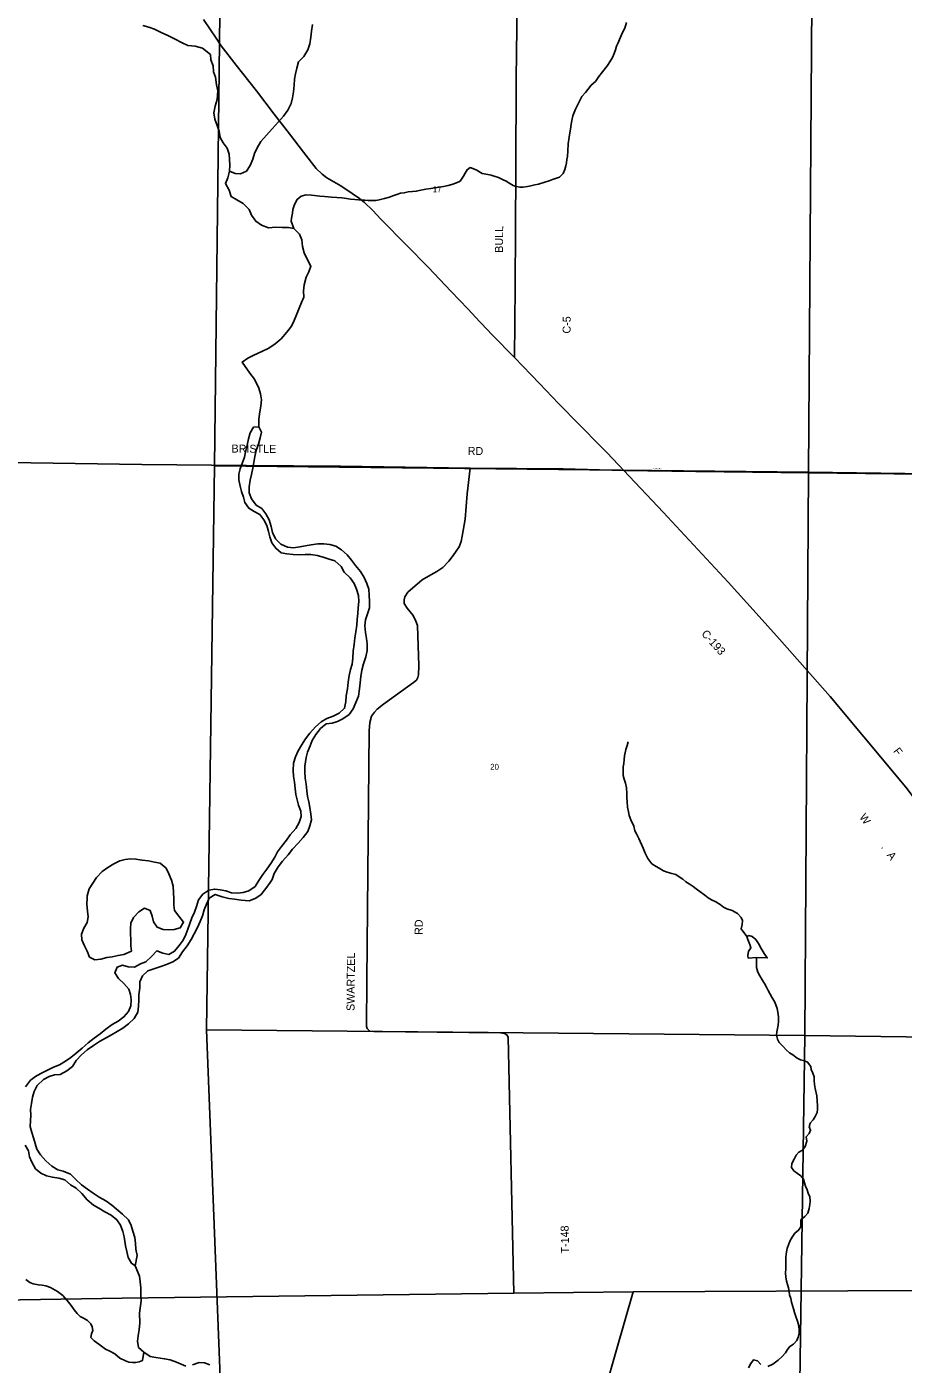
# Model space of a CAD drawing. Extents: x 1312308 to 1684953, y 460642 to 865172.
# Drawn here: x 1414657 to 1422870, y 616453 to 628989 of the extents above; entities that cross this region are included whole.
import ezdxf

# ---------------------------------------------------------------- set-up
doc = ezdxf.new("R2010")
doc.units = 0
for name, color, linetype in [('GM_X_County_Road', 7, 'Continuous'), ('GM_X_County_Road_Text', 7, 'Continuous'), ('GM_X_Minor_Lake', 7, 'Continuous'), ('GM_X_Minor_River', 7, 'Continuous'), ('GM_X_Section', 7, 'Continuous'), ('GM_X_Section_Text', 7, 'Continuous'), ('GM_X_Township_Road', 7, 'Continuous'), ('GM_X_Township_Road_Text', 7, 'Continuous'), ('GM_X_Township_Subdivision', 7, 'Continuous'), ('GM_X_Township_Subdivision_Text', 7, 'Continuous')]:
    doc.layers.add(name, color=color, linetype=linetype)

msp = doc.modelspace()

# ---------------------------------------------------------------- linework, layer by layer
at = {"layer": 'GM_X_County_Road'}
for points in [[(1419227, 625888), (1419235, 626551), (1419240, 627640), (1419244, 628500), (1419255, 629461), (1419265, 630495), (1419286, 631639), (1419313, 632893), (1419330, 633738), (1419360, 635102), (1419398, 637174), (1419431, 638484), (1419476, 640819), (1419479, 641151), (1419467, 641208), (1419429, 641336), (1419368, 641511)], [(1418902, 626224), (1418790, 626345), (1418634, 626507), (1418417, 626735), (1418214, 626941), (1417975, 627186), (1417900, 627265), (1417821, 627341), (1417775, 627379), (1417707, 627427), (1417601, 627498), (1417470, 627573), (1417424, 627608), (1417369, 627661), (1417251, 627812), (1417120, 627984), (1416976, 628169), (1416809, 628388), (1416737, 628478), (1416619, 628629), (1416479, 628811), (1416431, 628882), (1416312, 629056)], [(1420032, 625057), (1419835, 625257), (1419640, 625459), (1419463, 625645), (1419227, 625888), (1419018, 626102), (1418914, 626211), (1418902, 626224)], [(1425179, 618809), (1424819, 619478), (1424794, 619514), (1424735, 619589), (1424329, 620045), (1423843, 620591), (1423757, 620694), (1423588, 620906), (1423489, 621044), (1423310, 621295), (1423032, 621677), (1422907, 621845), (1422722, 622068), (1422501, 622335), (1422184, 622711), (1421710, 623249), (1421492, 623492), (1421229, 623784), (1420621, 624440), (1420252, 624831), (1420094, 624994), (1420032, 625057)], [(1411095, 617034), (1413623, 617054), (1414595, 617057), (1415550, 617073), (1419221, 617119), (1420340, 617133), (1423023, 617144)]]:
    msp.add_lwpolyline(points, dxfattribs=at)
at = {"layer": 'GM_X_Minor_Lake'}
for points in [[(1415640, 620325), (1415634, 620375), (1415633, 620433), (1415630, 620483), (1415629, 620538), (1415632, 620588), (1415657, 620641), (1415706, 620692), (1415759, 620729), (1415813, 620706), (1415832, 620652), (1415845, 620601), (1415880, 620548), (1415935, 620529), (1415989, 620524), (1416040, 620527), (1416096, 620544), (1416127, 620597), (1416082, 620652), (1416043, 620705), (1416036, 620756), (1416036, 620814), (1416033, 620874), (1416028, 620934), (1416015, 620989), (1415990, 621050), (1415963, 621104), (1415908, 621148), (1415854, 621159), (1415798, 621170), (1415738, 621177), (1415680, 621187), (1415630, 621190), (1415578, 621183), (1415528, 621172), (1415473, 621143), (1415416, 621110), (1415365, 621071), (1415312, 621016), (1415275, 620963), (1415242, 620909), (1415224, 620843), (1415222, 620823)], [(1415222, 620823), (1415219, 620765), (1415227, 620701), (1415232, 620645), (1415223, 620593), (1415192, 620539), (1415169, 620485), (1415174, 620431), (1415198, 620374), (1415223, 620324), (1415244, 620269), (1415296, 620242), (1415352, 620249), (1415409, 620264), (1415459, 620272), (1415513, 620285), (1415566, 620294), (1415640, 620325)], [(1421422, 620472), (1421404, 620462), (1421415, 620434), (1421426, 620402), (1421436, 620377), (1421443, 620357), (1421431, 620341), (1421419, 620324), (1421414, 620284), (1421417, 620260), (1421494, 620266)], [(1421494, 620266), (1421596, 620262), (1421567, 620302), (1421540, 620349), (1421512, 620396), (1421487, 620434), (1421454, 620461), (1421422, 620472)]]:
    msp.add_lwpolyline(points, dxfattribs=at)
at = {"layer": 'GM_X_Minor_River'}
for points in [[(1416833, 625240), (1416832, 625308), (1416837, 625362), (1416850, 625434), (1416858, 625492), (1416847, 625549), (1416833, 625600), (1416791, 625685), (1416749, 625743), (1416676, 625846), (1416729, 625882), (1416784, 625910), (1416860, 625944), (1416925, 625976), (1416984, 626016), (1417040, 626065), (1417094, 626125), (1417138, 626184), (1417162, 626235), (1417184, 626289), (1417210, 626350), (1417231, 626404), (1417253, 626455), (1417251, 626515), (1417255, 626569), (1417275, 626641), (1417301, 626692), (1417320, 626744), (1417292, 626799), (1417258, 626870), (1417242, 626929), (1417236, 626992), (1417213, 627045), (1417161, 627099), (1417109, 627106), (1417050, 627106), (1416990, 627110), (1416922, 627104), (1416856, 627129), (1416803, 627165), (1416763, 627224), (1416742, 627275), (1416684, 627331), (1416625, 627367), (1416573, 627397), (1416553, 627456), (1416519, 627521), (1416541, 627573), (1416557, 627636), (1416561, 627692), (1416556, 627743), (1416554, 627793), (1416535, 627850), (1416497, 627901), (1416468, 627952), (1416460, 628011), (1416442, 628062), (1416421, 628123), (1416409, 628183), (1416423, 628243), (1416441, 628307), (1416448, 628389), (1416435, 628443), (1416426, 628516), (1416407, 628567), (1416403, 628623), (1416382, 628678), (1416380, 628728), (1416304, 628789), (1416236, 628807), (1416168, 628813), (1416112, 628837), (1416043, 628876), (1415978, 628906), (1415916, 628934), (1415855, 628966), (1415802, 628986), (1415744, 629002)], [(1416557, 627636), (1416609, 627614), (1416661, 627611), (1416716, 627636), (1416751, 627689), (1416775, 627749), (1416792, 627801), (1416815, 627854), (1416852, 627914), (1416904, 627973), (1416957, 628032), (1417012, 628094), (1417064, 628151), (1417105, 628207), (1417134, 628268), (1417147, 628322), (1417157, 628380), (1417162, 628440), (1417167, 628496), (1417176, 628548), (1417187, 628602), (1417204, 628660), (1417252, 628711), (1417291, 628772), (1417310, 628828), (1417320, 628891), (1417325, 628947), (1417336, 629011)], [(1420199, 628839), (1420212, 628868), (1420231, 628914), (1420247, 628948), (1420262, 628976), (1420277, 629030)], [(1417161, 627099), (1417134, 627166), (1417139, 627194), (1417146, 627240), (1417150, 627276), (1417165, 627324), (1417190, 627370), (1417227, 627401), (1417275, 627412), (1417324, 627409), (1417352, 627407), (1417402, 627402), (1417446, 627397), (1417482, 627394), (1417512, 627392), (1417564, 627389), (1417608, 627386), (1417636, 627381), (1417690, 627374), (1417732, 627370), (1417766, 627367), (1417794, 627364), (1417826, 627362), (1417856, 627359), (1417890, 627359), (1417928, 627360), (1417958, 627365), (1418009, 627380), (1418055, 627390), (1418088, 627405), (1418124, 627418), (1418160, 627430), (1418195, 627433), (1418231, 627440), (1418273, 627444), (1418307, 627447), (1418349, 627456), (1418398, 627467), (1418442, 627473), (1418523, 627485), (1418561, 627492), (1418605, 627502), (1418639, 627509), (1418684, 627526), (1418718, 627542), (1418751, 627587), (1418766, 627617), (1418785, 627649), (1418813, 627668), (1418867, 627649), (1418924, 627614), (1418978, 627603), (1419008, 627599), (1419038, 627588), (1419076, 627575), (1419116, 627556), (1419149, 627540), (1419185, 627519), (1419215, 627500), (1419243, 627490), (1419277, 627485), (1419309, 627486), (1419349, 627492), (1419379, 627497), (1419418, 627507), (1419452, 627514), (1419510, 627533), (1419553, 627544), (1419583, 627556), (1419648, 627578), (1419683, 627614), (1419699, 627652), (1419708, 627684), (1419715, 627714), (1419719, 627744), (1419724, 627772), (1419727, 627824), (1419730, 627892), (1419738, 627954), (1419746, 627994), (1419751, 628030), (1419758, 628076), (1419765, 628110), (1419774, 628154), (1419799, 628216), (1419814, 628246), (1419835, 628290), (1419858, 628335), (1419891, 628373), (1419913, 628400), (1419946, 628442), (1419987, 628477), (1420016, 628521), (1420051, 628566), (1420098, 628626), (1420121, 628659), (1420144, 628699), (1420161, 628737), (1420174, 628773), (1420184, 628807), (1420199, 628839)], [(1416957, 620995), (1416977, 621052), (1417012, 621116), (1417053, 621167), (1417107, 621228), (1417148, 621281), (1417201, 621336), (1417248, 621389), (1417292, 621445), (1417311, 621500), (1417324, 621554), (1417319, 621610), (1417310, 621671), (1417299, 621723), (1417289, 621774), (1417282, 621828), (1417275, 621890), (1417266, 621945), (1417263, 622005), (1417264, 622057), (1417274, 622139), (1417287, 622191), (1417312, 622249), (1417332, 622300), (1417365, 622356), (1417410, 622411), (1417463, 622454), (1417519, 622461), (1417570, 622476), (1417620, 622501), (1417677, 622544), (1417717, 622595), (1417742, 622656), (1417767, 622716), (1417775, 622782), (1417780, 622840), (1417787, 622898), (1417796, 622958), (1417812, 623018), (1417833, 623082), (1417846, 623144), (1417847, 623204), (1417840, 623254), (1417832, 623310), (1417825, 623373), (1417830, 623431), (1417851, 623487), (1417870, 623542), (1417868, 623603), (1417867, 623661), (1417862, 623719), (1417845, 623771), (1417820, 623826), (1417783, 623883), (1417736, 623938), (1417701, 623989), (1417660, 624040), (1417605, 624086), (1417552, 624119), (1417498, 624136), (1417442, 624141), (1417384, 624141), (1417321, 624134), (1417267, 624125), (1417217, 624114), (1417158, 624105), (1417100, 624111), (1417037, 624138), (1416988, 624189), (1416961, 624250), (1416946, 624305), (1416929, 624367), (1416896, 624424), (1416859, 624475), (1416806, 624506), (1416763, 624563), (1416742, 624620), (1416741, 624678), (1416752, 624740), (1416762, 624792), (1416775, 624850), (1416786, 624904), (1416795, 624962), (1416808, 625018), (1416828, 625075), (1416843, 625135), (1416858, 625189), (1416833, 625240), (1416783, 625237), (1416752, 625183), (1416734, 625127), (1416723, 625068), (1416710, 625016), (1416697, 624954), (1416658, 624846), (1416643, 624795), (1416644, 624742), (1416657, 624684), (1416670, 624634), (1416687, 624581), (1416702, 624531)], [(1416702, 624531), (1416737, 624476), (1416789, 624446), (1416842, 624417), (1416879, 624366), (1416908, 624315), (1416921, 624259), (1416936, 624209), (1416955, 624152), (1416990, 624101), (1417041, 624058), (1417095, 624049), (1417153, 624041), (1417211, 624040), (1417267, 624043), (1417319, 624042), (1417379, 624032), (1417435, 624017), (1417491, 624000), (1417545, 623983), (1417602, 623929), (1417631, 623878), (1417686, 623823), (1417725, 623772), (1417748, 623719), (1417765, 623659), (1417769, 623603), (1417764, 623543), (1417759, 623489), (1417752, 623433), (1417751, 623380), (1417742, 623318), (1417730, 623261), (1417725, 623200), (1417716, 623136), (1417712, 623072), (1417705, 623014), (1417690, 622963), (1417679, 622907), (1417670, 622845), (1417662, 622783), (1417651, 622719), (1417646, 622665), (1417636, 622601), (1417583, 622556), (1417527, 622527), (1417470, 622504), (1417417, 622473), (1417362, 622426), (1417311, 622369), (1417270, 622314), (1417232, 622256), (1417199, 622203), (1417174, 622145), (1417157, 622087), (1417153, 622017), (1417158, 621965), (1417167, 621909), (1417172, 621848), (1417179, 621794), (1417190, 621744), (1417205, 621693), (1417224, 621637), (1417230, 621586), (1417211, 621529), (1417178, 621475), (1417125, 621416), (1417090, 621365), (1417044, 621307), (1417007, 621256), (1416982, 621205), (1416945, 621147), (1416906, 621094), (1416870, 621042), (1416833, 620987), (1416796, 620930), (1416737, 620891), (1416684, 620876), (1416634, 620867), (1416576, 620872), (1416524, 620889), (1416468, 620901), (1416418, 620906), (1416362, 620895), (1416307, 620860), (1416268, 620805), (1416247, 620743), (1416228, 620691), (1416204, 620638), (1416185, 620584), (1416168, 620532), (1416149, 620480), (1416122, 620429), (1416085, 620377), (1416043, 620324), (1415989, 620293), (1415931, 620306), (1415875, 620328), (1415826, 620275), (1415773, 620226), (1415722, 620205)], [(1421362, 620575), (1421364, 620611), (1421351, 620641), (1421318, 620678), (1421268, 620705), (1421216, 620722), (1421186, 620738), (1421155, 620763), (1421115, 620786), (1421074, 620807), (1421042, 620826), (1421010, 620848), (1420977, 620875), (1420931, 620908), (1420902, 620931), (1420864, 620955), (1420832, 620976), (1420803, 620999), (1420771, 621021), (1420739, 621042), (1420703, 621053), (1420658, 621064), (1420624, 621076), (1420584, 621101), (1420554, 621118), (1420515, 621143), (1420478, 621192), (1420453, 621242), (1420434, 621289), (1420391, 621382), (1420370, 621423), (1420355, 621453), (1420346, 621497), (1420317, 621556), (1420303, 621595), (1420294, 621629), (1420287, 621675), (1420282, 621723), (1420281, 621764), (1420280, 621806), (1420277, 621856), (1420266, 621899), (1420256, 621937), (1420247, 621971), (1420246, 622007), (1420247, 622052), (1420251, 622082), (1420254, 622122), (1420259, 622154), (1420272, 622214), (1420283, 622252), (1420291, 622286)], [(1415672, 617375), (1415692, 617473), (1415679, 617531), (1415676, 617586), (1415669, 617642), (1415650, 617700), (1415637, 617753), (1415610, 617806), (1415555, 617861), (1415453, 617943), (1415397, 617985), (1415336, 618020), (1415281, 618055), (1415225, 618093), (1415170, 618134), (1415117, 618185), (1415066, 618235), (1415000, 618262), (1414948, 618275), (1414893, 618308), (1414836, 618360), (1414785, 618417), (1414752, 618468), (1414735, 618521), (1414720, 618575), (1414705, 618625), (1414690, 618682), (1414693, 618734), (1414694, 618788), (1414691, 618840), (1414701, 618898), (1414712, 618956), (1414727, 619008), (1414756, 619066), (1414814, 619123), (1414866, 619150), (1414917, 619167), (1414971, 619169), (1415034, 619202), (1415085, 619245), (1415120, 619301), (1415171, 619352), (1415222, 619399), (1415283, 619442), (1415340, 619479), (1415395, 619509), (1415452, 619540), (1415503, 619573), (1415559, 619604), (1415612, 619643), (1415665, 619694), (1415697, 619752), (1415704, 619808), (1415707, 619864), (1415708, 619916), (1415716, 619980), (1415717, 620038), (1415742, 620094), (1415793, 620139), (1415856, 620162), (1415914, 620180), (1415967, 620199), (1416025, 620224), (1416078, 620259), (1416118, 620318), (1416159, 620376), (1416198, 620433), (1416227, 620487), (1416257, 620546), (1416282, 620602), (1416303, 620657), (1416320, 620711), (1416341, 620765), (1416365, 620821), (1416423, 620856), (1416489, 620834), (1416551, 620819), (1416605, 620811), (1416665, 620802), (1416741, 620796), (1416798, 620817), (1416850, 620854), (1416898, 620913), (1416937, 620967), (1416957, 620995)], [(1421404, 620462), (1421351, 620533), (1421362, 620575)], [(1415722, 620205), (1415667, 620174), (1415609, 620179), (1415554, 620194), (1415503, 620175), (1415482, 620120), (1415517, 620067), (1415568, 620021), (1415615, 619970), (1415628, 619920), (1415635, 619867), (1415632, 619811), (1415611, 619760), (1415568, 619708), (1415513, 619669), (1415458, 619636), (1415397, 619594), (1415346, 619551), (1415289, 619508), (1415234, 619465), (1415177, 619416), (1415121, 619369), (1415070, 619328), (1415020, 619293), (1414963, 619260), (1414908, 619237), (1414858, 619212), (1414801, 619185), (1414748, 619156), (1414693, 619117), (1414646, 619052)], [(1421815, 617070), (1421804, 617104), (1421802, 617134), (1421795, 617170), (1421786, 617201), (1421776, 617233), (1421769, 617273), (1421768, 617307), (1421769, 617350), (1421771, 617456), (1421776, 617506), (1421781, 617538), (1421798, 617582), (1421812, 617618), (1421835, 617652), (1421854, 617681), (1421889, 617711), (1421911, 617740), (1421910, 617773), (1421911, 617807), (1421949, 617838), (1421976, 617870), (1421987, 617914), (1421996, 617950), (1421998, 617980), (1421993, 618022), (1421980, 618055), (1421969, 618089), (1421953, 618123), (1421944, 618154), (1421934, 618188), (1421909, 618219), (1421879, 618241), (1421846, 618266), (1421822, 618298), (1421825, 618335), (1421848, 618376), (1421865, 618412), (1421892, 618442), (1421926, 618461), (1421951, 618493), (1421966, 618545), (1421961, 618585), (1421987, 618615), (1422002, 618647), (1421987, 618677), (1421997, 618713), (1422026, 618743), (1422045, 618774), (1422062, 618814), (1422066, 618844), (1422067, 618876), (1422062, 618921), (1422059, 618969), (1422044, 619037), (1422039, 619074), (1422034, 619112), (1422034, 619148), (1422023, 619180), (1422006, 619215), (1422004, 619245), (1421973, 619284), (1421943, 619296), (1421907, 619307), (1421877, 619322), (1421836, 619353), (1421804, 619371), (1421775, 619398), (1421743, 619435), (1421708, 619469), (1421691, 619500), (1421681, 619538), (1421686, 619568), (1421691, 619600), (1421697, 619632), (1421700, 619670), (1421701, 619709), (1421696, 619753), (1421688, 619787), (1421677, 619822), (1421664, 619852), (1421642, 619886), (1421623, 619923), (1421604, 619955), (1421588, 619986), (1421569, 620022), (1421548, 620055), (1421526, 620093), (1421507, 620128), (1421494, 620170), (1421494, 620266)], [(1414642, 618506), (1414673, 618452), (1414684, 618397), (1414705, 618347), (1414738, 618286), (1414789, 618243), (1414843, 618219), (1414897, 618206), (1414959, 618197), (1415013, 618180), (1415066, 618136), (1415119, 618103), (1415174, 618052), (1415223, 617994), (1415282, 617945), (1415334, 617916), (1415389, 617883), (1415447, 617851), (1415500, 617808), (1415535, 617755), (1415556, 617698), (1415569, 617646), (1415583, 617563), (1415594, 617509), (1415609, 617455), (1415640, 617400), (1415672, 617375)], [(1416149, 616436), (1416060, 616471), (1416000, 616493), (1415948, 616504), (1415868, 616515), (1415814, 616527), (1415755, 616567), (1415703, 616611), (1415696, 616669), (1415700, 616719), (1415712, 616777), (1415718, 616841), (1415713, 616932), (1415728, 617048), (1415726, 617112), (1415726, 617168), (1415720, 617225), (1415715, 617277), (1415672, 617375)], [(1415755, 616567), (1415742, 616489), (1415709, 616475), (1415677, 616468), (1415647, 616468), (1415615, 616473), (1415581, 616486), (1415529, 616511), (1415482, 616550), (1415435, 616577), (1415395, 616595), (1415332, 616641), (1415290, 616672), (1415257, 616704), (1415263, 616738), (1415276, 616768), (1415271, 616803), (1415257, 616833), (1415228, 616862), (1415194, 616882), (1415158, 616901), (1415129, 616930), (1415100, 616964), (1415072, 617003), (1415037, 617050), (1414994, 617097), (1414945, 617136), (1414879, 617173), (1414837, 617188), (1414803, 617193), (1414767, 617197), (1414717, 617208), (1414686, 617219), (1414650, 617246)], [(1421600, 616433), (1421648, 616454), (1421697, 616491), (1421736, 616527), (1421765, 616560), (1421785, 616590), (1421808, 616620), (1421841, 616641), (1421873, 616677), (1421884, 616707), (1421895, 616743), (1421895, 616773), (1421890, 616813), (1421879, 616856), (1421862, 616902), (1421851, 616938), (1421841, 616973), (1421832, 617005), (1421823, 617035), (1421815, 617070)], [(1416374, 616446), (1416323, 616466), (1416273, 616468), (1416210, 616446)], [(1421421, 616420), (1421442, 616460), (1421466, 616494), (1421504, 616485), (1421534, 616450)]]:
    msp.add_lwpolyline(points, dxfattribs=at)
at = {"layer": 'GM_X_Section'}
for points in [[(1416479, 630171), (1422018, 630094), (1421982, 624815), (1416416, 624874)], [(1422018, 630094), (1427371, 630043), (1427169, 624743), (1421982, 624815)], [(1421982, 624815), (1421949, 619535), (1416340, 619588), (1416416, 624874)], [(1427169, 624743), (1426939, 619468), (1421949, 619535), (1421982, 624815)], [(1416340, 619588), (1421949, 619535), (1421880, 614765), (1416537, 614586)], [(1421949, 619535), (1426939, 619468), (1427084, 614755), (1421880, 614765)]]:
    msp.add_lwpolyline(points, close=True, dxfattribs=at)
at = {"layer": 'GM_X_Township_Road'}
for points in [[(1411160, 624954), (1415734, 624885), (1416715, 624877)], [(1416715, 624877), (1417597, 624870), (1418812, 624852)], [(1419221, 617119), (1419167, 619520), (1419155, 619540), (1419135, 619554), (1419095, 619559), (1417908, 619573), (1417873, 619576), (1417848, 619599), (1417842, 619619), (1417845, 620051), (1417867, 622389), (1417872, 622467), (1417888, 622526), (1417914, 622564), (1417940, 622592), (1418000, 622640), (1418281, 622842), (1418308, 622865), (1418322, 622889), (1418327, 622916), (1418330, 622999), (1418318, 623376), (1418302, 623419), (1418277, 623470), (1418221, 623539), (1418195, 623582), (1418192, 623618), (1418200, 623647), (1418229, 623689), (1418363, 623805), (1418442, 623853), (1418500, 623882), (1418555, 623922), (1418613, 623979), (1418653, 624033), (1418710, 624113), (1418729, 624163), (1418737, 624215), (1418765, 624374), (1418783, 624611), (1418812, 624852)], [(1418812, 624852), (1419684, 624845), (1420252, 624831)], [(1418709, 614114), (1418719, 614230), (1418729, 614452), (1418728, 614637), (1418704, 614858), (1418668, 615003), (1418654, 615056), (1418657, 615103), (1418682, 615159), (1418722, 615210), (1418998, 615486), (1419131, 615591), (1419274, 615683), (1419555, 615839), (1419736, 615939), (1419769, 615959), (1419993, 616164), (1420046, 616222), (1420087, 616286), (1420113, 616348), (1420182, 616589), (1420340, 617133)]]:
    msp.add_lwpolyline(points, dxfattribs=at)
at = {"layer": 'GM_X_Township_Subdivision'}
msp.add_lwpolyline([(1420252, 624831), (1420925, 624821), (1422782, 624798), (1424136, 624789), (1424856, 624782), (1426415, 624768), (1427163, 624758)], dxfattribs=at)

# ---------------------------------------------------------------- texts
at = {"layer": 'GM_X_County_Road_Text'}
for s, rotation, p in [('BULL', 89.4759, (1419119, 626870)), ('C-5', 89.5419, (1419753, 626113)), ('C-193', 311.5451, (1420974, 623296)), ('F', 306.7435, (1422772, 622198)), ('W', 306.0377, (1422454, 621580)), ('.', 306.0331, (1422659, 621299)), ('A', 306.0429, (1422713, 621224))]:
    msp.add_text(s, height=75, rotation=rotation, dxfattribs=at).set_placement(p)
at = {"layer": 'GM_X_Section_Text'}
for s, p in [('17', (1418462, 627438)), ('20', (1418999, 622025))]:
    msp.add_text(s, height=55.3, rotation=0, dxfattribs=at).set_placement(p)
at = {"layer": 'GM_X_Township_Road_Text'}
for s, rotation, p in [('BRISTLE', 359.4918, (1416576, 624998)), ('RD', 359.5064, (1418789, 624976)), ('RD', 89.0118, (1418366, 620476)), ('SWARTZEL', 89.4839, (1417728, 619764)), ('T-148', 91.4043, (1419740, 617492))]:
    msp.add_text(s, height=75, rotation=rotation, dxfattribs=at).set_placement(p)
at = {"layer": 'GM_X_Township_Subdivision_Text'}
msp.add_text('CHICKEN', height=12.5, rotation=358.1499, dxfattribs=at).set_placement((1420530, 624841))

doc.saveas('drawing.dxf')
